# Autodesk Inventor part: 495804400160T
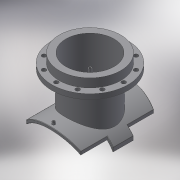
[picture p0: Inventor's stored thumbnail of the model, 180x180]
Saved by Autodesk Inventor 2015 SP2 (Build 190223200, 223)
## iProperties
Created: 2017-10
Part Number: 495804400160T
Material: Generic
Description: PLASSON FLANGED BRANCH SADDLE 450-800X80
Document SubType Name: Modeling
Designer: KIM
Density: 1 g/cm^3
Appearance: Default
Author: KIM
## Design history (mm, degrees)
derived "495904.ipt"
feature "Solid1::495904.ipt"
feature "Solid2::495904.ipt"
tag "TaggingFeature1"
body "Solid1"
other parameters: "d1" = 15, "d2" = 283.5, "d4" = 0, "d5" = 315, "d6" = 75, "d7" = 0, "d11" = 4, "d12" = 425.6, "d13" = 14, "d14" = 135, "d16" = 5 deg, "d18" = 4, "d19" = 14, "d20" = 0, "d21" = 3, "d22" = 0, "d36" = 135, "d38" = 0, "d39" = 2, "d40" = 105, "d42" = 138, "d44" = 84, "d46" = 110.4, "d47" = 16, "d48" = 10.4, "d49" = 73.5, "d51" = 816, "d53" = 0, "d54" = 18, "d57" = 0, "d59" = 360 deg, "d63" = 0, "d_1" = 138, "B_" = 315, "H_" = 105, "x_" = 15, "D_" = 16, "s_" = 18
